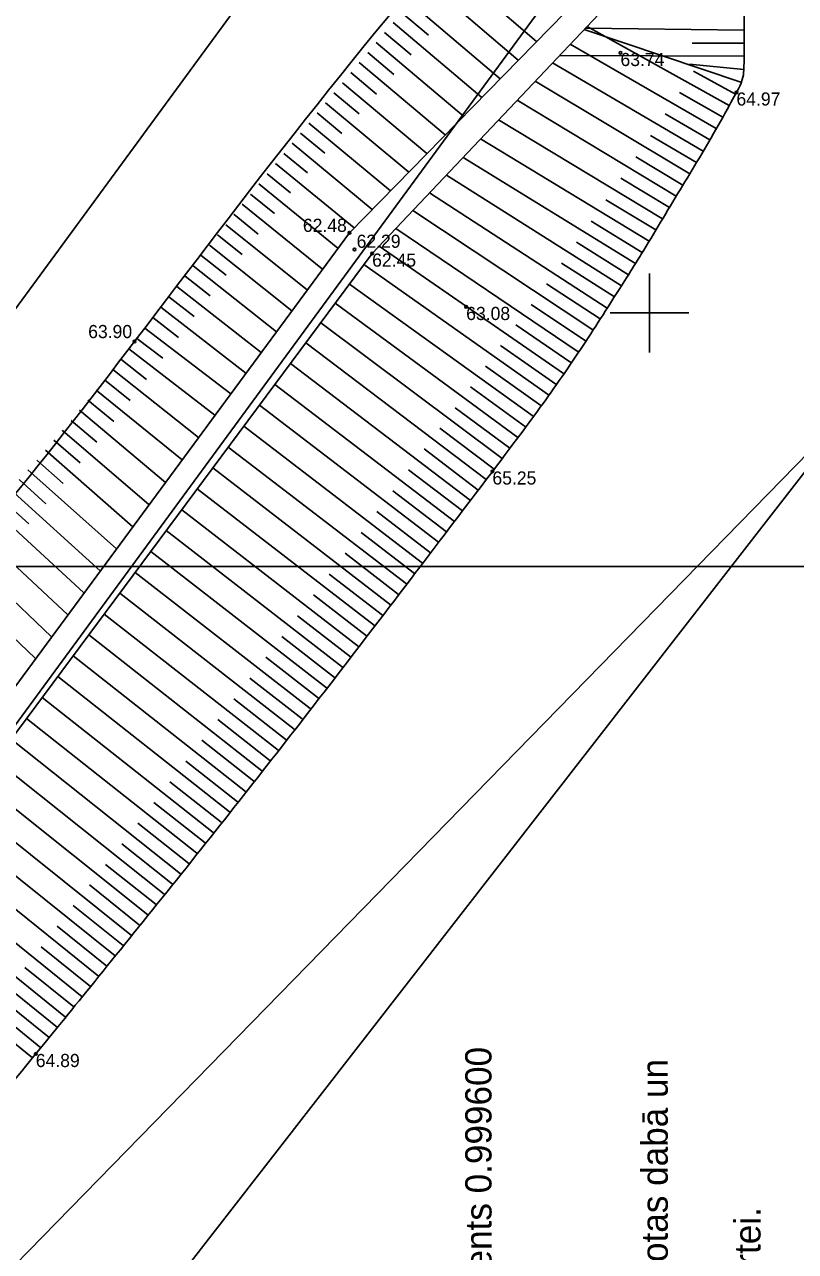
# Model space of a CAD drawing. Extents: x 616607 to 617499, y 408385 to 409695.
# Drawn here: x 617176.19 to 617205.56, y 409264.26 to 409310.99 of the extents above; entities that cross this region are included whole.
import ezdxf

# ---------------------------------------------------------------- set-up
doc = ezdxf.new("R2010")
doc.units = 0
for name, color, linetype in [('GEOD_ELEM_####_####_#', 7, 'Continuous'), ('HIDG_GRAV_####_####_#', 7, 'Continuous'), ('RAMI_PLAN_####_TKST_#', 7, 'Continuous'), ('RAMI_UZMR_####_####_#', 7, 'Continuous'), ('RELJ_AATZ_####_TKST_#', 7, 'Continuous'), ('RELJ_ELEM_####_####_#', 7, 'Continuous'), ('RELJ_NOGA_####_####_#', 7, 'Continuous'), ('ROBZ_UZMR_####_####_#', 7, 'Continuous')]:
    doc.layers.add(name, color=color, linetype=linetype)

# ---------------------------------------------------------------- blocks, each defined once
blk = doc.blocks.new('PKT')
at = {"layer": 'RELJ_ELEM_####_####_#'}
blk.add_circle((0, 0), 0.05, dxfattribs=at)
blk = doc.blocks.new('KRUSTS')
at = {"layer": 'GEOD_ELEM_####_####_#'}
for p, q in [((0, 1.5), (0, 0)), ((-1.5, 0), (0, 0)), ((0, 0), (0, -1.5)), ((0, 0), (1.5, 0))]:
    blk.add_line(p, q, dxfattribs=at)

msp = doc.modelspace()

# ---------------------------------------------------------------- linework, layer by layer
at = {"layer": 'HIDG_GRAV_####_####_#'}
for points in [[(617196.049, 409072.553), (617193.886, 409072.979), (617195.921, 409087.874), (617195.921, 409087.874), (617199.518, 409112.516), (617194.569, 409134.842), (617162.019, 409207.474), (617151.93, 409229.107), (617149.428, 409241.28), (617152.359, 409253.938), (617188.564, 409303.055), (617197.968, 409312.659), (617223.456, 409346.169), (617232.567, 409363.51), (617247.671, 409422.509), (617276.576, 409461.456), (617285.007, 409472.526), (617327.765, 409527.3)], [(617198.671, 409072.074), (617200.929, 409072.435), (617202.532, 409075.622), (617201.237, 409087.874), (617202.422, 409112.516), (617197.415, 409136.544), (617162.613, 409207.758), (617153.021, 409229.447), (617150.525, 409241.262), (617153.298, 409253.658), (617189.431, 409302.264), (617198.754, 409312.12), (617224.478, 409345.652), (617234.105, 409363.027), (617250.009, 409421.44), (617285.914, 409471.848), (617328.6, 409526.531)]]:
    msp.add_lwpolyline(points, dxfattribs=at)
at = {"layer": 'RAMI_PLAN_####_TKST_#'}
msp.add_line((617357.121, 409449.318), (617128.46, 409215.262), dxfattribs=at)
msp.add_lwpolyline([(617109.674, 409084.461), (617109.674, 409290.339), (617251.246, 409290.339), (617251.246, 409084.461), (617109.674, 409084.461)], dxfattribs=at)
at = {"layer": 'RAMI_UZMR_####_####_#'}
msp.add_lwpolyline([(617101.571, 408748.246), (617213.472, 409074.039), (617215.883, 409140.56), (617165.121, 409241.478), (617252.137, 409353.424), (617269.572, 409425.099), (617332.631, 409510.312), (617439.945, 409622.037), (617425.373, 409635.959), (617242.079, 409440.82), (617216.614, 409355.716), (617136.613, 409246.751), (617191.828, 409115.62), (617145.545, 408952.8)], dxfattribs=at)
at = {"layer": 'RELJ_NOGA_####_####_#'}
for p, q in [((617192.175, 409313.349), (617195.697, 409310.34)), ((617191.526, 409312.588), (617194.999, 409309.626)), ((617190.877, 409311.827), (617194.301, 409308.913)), ((617190.23, 409311.064), (617193.607, 409308.205)), ((617190.554, 409311.445), (617191.574, 409310.58)), ((617189.907, 409310.683), (617189.907, 409310.683)), ((617189.907, 409310.683), (617190.912, 409309.832)), ((617203.48, 409308.789), (617197.504, 409310.799)), ((617203.602, 409310.776), (617197.546, 409310.843)), ((617203.031, 409307.897), (617197.616, 409310.916)), ((617203.602, 409310.776), (617203.603, 409310.776)), ((617189.584, 409310.301), (617189.584, 409310.301)), ((617189.584, 409310.301), (617192.911, 409307.494)), ((617202.54, 409307.026), (617196.968, 409310.232)), ((617203.598, 409310.276), (617201.622, 409310.276)), ((617203.598, 409310.276), (617203.599, 409310.276)), ((617189.262, 409309.919), (617189.262, 409309.919)), ((617189.262, 409309.919), (617190.251, 409309.084)), ((617203.599, 409309.776), (617196.567, 409309.807)), ((617203.599, 409309.776), (617203.6, 409309.776)), ((617188.94, 409309.536), (617188.939, 409309.537)), ((617188.94, 409309.536), (617192.213, 409306.781)), ((617202.038, 409306.162), (617196.302, 409309.528)), ((617203.587, 409309.276), (617201.517, 409309.474)), ((617203.273, 409308.335), (617201.673, 409309.212)), ((617203.587, 409309.276), (617203.588, 409309.276)), ((617188.297, 409308.771), (617188.296, 409308.771)), ((617188.297, 409308.771), (617191.517, 409306.071)), ((617188.618, 409309.154), (617188.618, 409309.154)), ((617188.618, 409309.154), (617189.592, 409308.335)), ((617201.528, 409305.301), (617195.638, 409308.826)), ((617203.48, 409308.789), (617203.481, 409308.789)), ((617187.976, 409308.387), (617187.975, 409308.387)), ((617187.976, 409308.387), (617188.934, 409307.586)), ((617202.787, 409307.461), (617201.137, 409308.393)), ((617203.273, 409308.335), (617203.273, 409308.335)), ((617187.655, 409308.003), (617187.655, 409308.004)), ((617187.655, 409308.003), (617190.822, 409305.361)), ((617201.013, 409304.444), (617194.951, 409308.099)), ((617203.031, 409307.897), (617203.032, 409307.897)), ((617187.335, 409307.619), (617187.335, 409307.619)), ((617187.335, 409307.619), (617188.277, 409306.835)), ((617200.497, 409303.588), (617194.244, 409307.352)), ((617202.29, 409306.593), (617200.592, 409307.578)), ((617202.787, 409307.461), (617202.787, 409307.461)), ((617186.697, 409306.849), (617186.697, 409306.849)), ((617186.697, 409306.849), (617187.623, 409306.085)), ((617187.016, 409307.234), (617187.015, 409307.235)), ((617187.016, 409307.234), (617190.127, 409304.651)), ((617202.54, 409307.026), (617202.541, 409307.026)), ((617186.379, 409306.464), (617186.378, 409306.464)), ((617186.379, 409306.464), (617189.437, 409303.946)), ((617199.98, 409302.732), (617193.559, 409306.628)), ((617201.784, 409305.731), (617200.038, 409306.762)), ((617202.29, 409306.593), (617202.29, 409306.593)), ((617186.061, 409306.078), (617186.061, 409306.078)), ((617186.061, 409306.078), (617186.97, 409305.332)), ((617199.458, 409301.879), (617192.895, 409305.926)), ((617201.271, 409304.873), (617199.481, 409305.952)), ((617202.038, 409306.162), (617202.039, 409306.161)), ((617185.744, 409305.691), (617185.743, 409305.692)), ((617185.744, 409305.691), (617188.743, 409303.237)), ((617201.784, 409305.731), (617201.784, 409305.731)), ((617185.427, 409305.304), (617185.427, 409305.304)), ((617185.427, 409305.304), (617186.326, 409304.571)), ((617198.927, 409301.031), (617192.257, 409305.252)), ((617200.755, 409304.016), (617198.907, 409305.128)), ((617201.528, 409305.301), (617201.529, 409305.301)), ((617184.796, 409304.528), (617184.796, 409304.529)), ((617184.796, 409304.528), (617185.708, 409303.79)), ((617185.111, 409304.916), (617185.111, 409304.917)), ((617185.111, 409304.916), (617188.129, 409302.464)), ((617198.387, 409300.189), (617191.616, 409304.574)), ((617201.271, 409304.873), (617201.271, 409304.872)), ((617184.482, 409304.14), (617184.481, 409304.14)), ((617184.482, 409304.14), (617187.544, 409301.67)), ((617200.239, 409303.16), (617198.336, 409304.307)), ((617201.013, 409304.444), (617201.013, 409304.444)), ((617184.168, 409303.751), (617184.167, 409303.751)), ((617184.168, 409303.751), (617185.093, 409303.007)), ((617197.839, 409299.353), (617190.983, 409303.905)), ((617200.497, 409303.588), (617200.498, 409303.587)), ((617200.755, 409304.016), (617200.755, 409304.016)), ((617183.855, 409303.361), (617183.854, 409303.361)), ((617183.855, 409303.361), (617186.959, 409300.877)), ((617197.282, 409298.523), (617190.337, 409303.221)), ((617199.719, 409302.305), (617197.772, 409303.497)), ((617200.239, 409303.16), (617200.239, 409303.159)), ((617183.542, 409302.97), (617183.542, 409302.97)), ((617183.542, 409302.97), (617184.478, 409302.221)), ((617199.194, 409301.454), (617197.209, 409302.695)), ((617199.98, 409302.732), (617199.98, 409302.731)), ((617182.92, 409302.187), (617182.92, 409302.188)), ((617182.92, 409302.187), (617183.868, 409301.436)), ((617183.231, 409302.579), (617183.23, 409302.58)), ((617183.231, 409302.579), (617186.37, 409300.078)), ((617196.717, 409297.697), (617189.699, 409302.547)), ((617199.719, 409302.305), (617199.72, 409302.305)), ((617182.61, 409301.795), (617182.609, 409301.796)), ((617182.61, 409301.795), (617185.787, 409299.287)), ((617196.144, 409296.878), (617189.117, 409301.841)), ((617198.658, 409300.609), (617196.642, 409301.901)), ((617199.458, 409301.879), (617199.459, 409301.878)), ((617182.301, 409301.402), (617182.301, 409301.402)), ((617182.301, 409301.402), (617183.26, 409300.649)), ((617199.194, 409301.454), (617199.194, 409301.454)), ((617181.993, 409301.008), (617181.992, 409301.009)), ((617181.993, 409301.008), (617185.205, 409298.498)), ((617195.563, 409296.064), (617188.565, 409301.099)), ((617198.114, 409299.771), (617196.068, 409301.109)), ((617198.927, 409301.031), (617198.928, 409301.03)), ((617181.686, 409300.614), (617181.685, 409300.614)), ((617181.686, 409300.614), (617182.654, 409299.861)), ((617194.975, 409295.255), (617188.022, 409300.369)), ((617197.561, 409298.937), (617195.492, 409300.326)), ((617198.658, 409300.609), (617198.659, 409300.609)), ((617181.379, 409300.219), (617181.379, 409300.219)), ((617181.379, 409300.219), (617184.624, 409297.709)), ((617198.387, 409300.189), (617198.388, 409300.189)), ((617180.77, 409299.426), (617180.769, 409299.427)), ((617180.77, 409299.426), (617184.044, 409296.922)), ((617181.074, 409299.823), (617181.074, 409299.823)), ((617181.074, 409299.823), (617182.052, 409299.071)), ((617194.379, 409294.453), (617187.471, 409299.627)), ((617197.001, 409298.109), (617194.909, 409299.545)), ((617198.114, 409299.771), (617198.115, 409299.77)), ((617180.466, 409299.029), (617180.466, 409299.029)), ((617180.466, 409299.029), (617181.452, 409298.278)), ((617197.561, 409298.937), (617197.562, 409298.937)), ((617197.839, 409299.353), (617197.84, 409299.353)), ((617180.163, 409298.631), (617180.162, 409298.632)), ((617180.163, 409298.631), (617183.443, 409296.107)), ((617193.776, 409293.655), (617186.906, 409298.867)), ((617196.432, 409297.287), (617194.319, 409298.764)), ((617197.282, 409298.523), (617197.283, 409298.522)), ((617179.856, 409298.236), (617179.856, 409298.236)), ((617179.856, 409298.236), (617180.839, 409297.47)), ((617193.171, 409292.858), (617186.314, 409298.071)), ((617195.854, 409296.47), (617193.752, 409297.972)), ((617197.001, 409298.109), (617197.001, 409298.109)), ((617179.547, 409297.843), (617179.546, 409297.844)), ((617179.547, 409297.843), (617182.815, 409295.255)), ((617196.717, 409297.697), (617196.718, 409297.697)), ((617178.92, 409297.064), (617178.92, 409297.065)), ((617178.92, 409297.064), (617182.189, 409294.406)), ((617179.235, 409297.452), (617179.235, 409297.453)), ((617179.235, 409297.452), (617180.213, 409296.663)), ((617192.566, 409292.062), (617185.722, 409297.274)), ((617195.27, 409295.659), (617193.178, 409297.183)), ((617196.432, 409297.287), (617196.432, 409297.287)), ((617178.603, 409296.677), (617178.603, 409296.678)), ((617178.603, 409296.677), (617179.584, 409295.867)), ((617196.144, 409296.878), (617196.145, 409296.877)), ((617178.283, 409296.293), (617178.283, 409296.294)), ((617178.283, 409296.293), (617181.556, 409293.547)), ((617191.959, 409291.267), (617185.134, 409296.484)), ((617194.678, 409294.853), (617192.596, 409296.393)), ((617195.854, 409296.47), (617195.855, 409296.47)), ((617177.961, 409295.911), (617177.961, 409295.911)), ((617177.961, 409295.911), (617178.946, 409295.075)), ((617191.352, 409290.473), (617184.542, 409295.687)), ((617195.27, 409295.659), (617195.27, 409295.659)), ((617195.563, 409296.064), (617195.564, 409296.063)), ((617177.637, 409295.53), (617177.636, 409295.531)), ((617177.637, 409295.53), (617180.931, 409292.699)), ((617194.078, 409294.053), (617192.012, 409295.613)), ((617194.975, 409295.255), (617194.976, 409295.255)), ((617176.982, 409294.774), (617176.981, 409294.775)), ((617176.982, 409294.774), (617180.309, 409291.856)), ((617177.31, 409295.151), (617177.31, 409295.152)), ((617177.31, 409295.151), (617178.305, 409294.291)), ((617190.743, 409289.679), (617183.949, 409294.89)), ((617193.474, 409293.256), (617191.415, 409294.821)), ((617194.678, 409294.853), (617194.678, 409294.853)), ((617176.652, 409294.399), (617176.651, 409294.399)), ((617176.652, 409294.399), (617177.657, 409293.511)), ((617194.379, 409294.453), (617194.379, 409294.452)), ((617176.319, 409294.025), (617176.319, 409294.026)), ((617176.319, 409294.025), (617179.694, 409291.021)), ((617190.134, 409288.886), (617183.361, 409294.098)), ((617192.868, 409292.46), (617190.814, 409294.025)), ((617194.078, 409294.053), (617194.078, 409294.053)), ((617175.986, 409293.653), (617177.003, 409292.735)), ((617189.524, 409288.094), (617182.768, 409293.301)), ((617193.776, 409293.655), (617193.777, 409293.654)), ((617175.313, 409292.913), (617176.347, 409291.966)), ((617175.65, 409293.282), (617179.07, 409290.174)), ((617192.262, 409291.665), (617190.212, 409293.229)), ((617193.171, 409292.858), (617193.172, 409292.858)), ((617193.474, 409293.256), (617193.474, 409293.256)), ((617174.975, 409292.545), (617178.451, 409289.335)), ((617188.913, 409287.302), (617182.179, 409292.508)), ((617191.655, 409290.87), (617189.61, 409292.434)), ((617192.868, 409292.46), (617192.869, 409292.46)), ((617192.566, 409292.062), (617192.566, 409292.062)), ((617174.294, 409291.812), (617177.838, 409288.503)), ((617188.301, 409286.511), (617181.586, 409291.71)), ((617191.048, 409290.076), (617189.006, 409291.639)), ((617192.262, 409291.665), (617192.263, 409291.665)), ((617173.609, 409291.084), (617177.219, 409287.663)), ((617191.959, 409291.267), (617191.96, 409291.267)), ((617187.689, 409285.721), (617180.994, 409290.915)), ((617190.439, 409289.283), (617188.404, 409290.846)), ((617191.655, 409290.87), (617191.656, 409290.87)), ((617172.92, 409290.359), (617176.611, 409286.838)), ((617187.075, 409284.931), (617180.404, 409290.121)), ((617189.829, 409288.49), (617187.799, 409290.052)), ((617191.048, 409290.076), (617191.048, 409290.076)), ((617191.352, 409290.473), (617191.352, 409290.472)), ((617190.743, 409289.679), (617190.744, 409289.679)), ((617186.46, 409284.143), (617179.814, 409289.327)), ((617189.219, 409287.698), (617187.195, 409289.26)), ((617190.439, 409289.283), (617190.439, 409289.282)), ((617190.134, 409288.886), (617190.135, 409288.886)), ((617185.845, 409283.354), (617179.223, 409288.532)), ((617188.607, 409286.906), (617186.589, 409288.467)), ((617189.829, 409288.49), (617189.83, 409288.49)), ((617185.228, 409282.567), (617178.632, 409287.737)), ((617189.219, 409287.698), (617189.219, 409287.698)), ((617189.524, 409288.094), (617189.525, 409288.093)), ((617187.995, 409286.116), (617185.984, 409287.676)), ((617188.913, 409287.302), (617188.914, 409287.301)), ((617184.611, 409281.78), (617178.04, 409286.941)), ((617187.382, 409285.326), (617185.378, 409286.885)), ((617188.607, 409286.906), (617188.608, 409286.906)), ((617188.301, 409286.511), (617188.302, 409286.51)), ((617183.992, 409280.995), (617177.453, 409286.151)), ((617186.768, 409284.537), (617184.771, 409286.094)), ((617187.995, 409286.116), (617187.995, 409286.116)), ((617183.373, 409280.21), (617176.861, 409285.355)), ((617187.689, 409285.721), (617187.689, 409285.72)), ((617186.153, 409283.748), (617184.163, 409285.304)), ((617187.075, 409284.931), (617187.076, 409284.931)), ((617187.382, 409285.326), (617187.382, 409285.326)), ((617182.752, 409279.425), (617176.268, 409284.557)), ((617185.537, 409282.961), (617183.555, 409284.514)), ((617186.768, 409284.537), (617186.768, 409284.537)), ((617186.46, 409284.143), (617186.461, 409284.142)), ((617182.131, 409278.642), (617175.679, 409283.765)), ((617184.92, 409282.174), (617182.945, 409283.724)), ((617186.153, 409283.748), (617186.153, 409283.748)), ((617185.845, 409283.354), (617185.845, 409283.354)), ((617181.509, 409277.859), (617175.087, 409282.969)), ((617184.302, 409281.387), (617182.335, 409282.935)), ((617185.228, 409282.567), (617185.229, 409282.566)), ((617185.537, 409282.961), (617185.537, 409282.96)), ((617180.885, 409277.077), (617174.497, 409282.174)), ((617183.683, 409280.602), (617181.724, 409282.146)), ((617184.92, 409282.174), (617184.92, 409282.174)), ((617184.611, 409281.78), (617184.612, 409281.78)), ((617180.261, 409276.296), (617173.905, 409281.379)), ((617183.063, 409279.817), (617181.114, 409281.36)), ((617184.302, 409281.387), (617184.302, 409281.387)), ((617183.992, 409280.995), (617183.993, 409280.994)), ((617179.635, 409275.516), (617173.317, 409280.588)), ((617182.442, 409279.033), (617180.501, 409280.572)), ((617183.373, 409280.21), (617183.374, 409280.209)), ((617183.683, 409280.602), (617183.683, 409280.602)), ((617179.009, 409274.736), (617172.729, 409279.797)), ((617181.82, 409278.25), (617179.89, 409279.786)), ((617183.063, 409279.817), (617183.063, 409279.817)), ((617182.752, 409279.425), (617182.753, 409279.425)), ((617178.381, 409273.958), (617172.137, 409279.001)), ((617181.197, 409277.468), (617179.276, 409279)), ((617182.442, 409279.033), (617182.442, 409279.033)), ((617182.131, 409278.642), (617182.132, 409278.641)), ((617177.753, 409273.18), (617171.546, 409278.205)), ((617180.573, 409276.687), (617178.662, 409278.215)), ((617181.82, 409278.25), (617181.82, 409278.25)), ((617177.123, 409272.403), (617170.954, 409277.409)), ((617179.948, 409275.906), (617178.047, 409277.429)), ((617181.197, 409277.468), (617181.197, 409277.468)), ((617181.509, 409277.859), (617181.509, 409277.859)), ((617180.885, 409277.077), (617180.886, 409277.077)), ((617176.493, 409271.627), (617170.363, 409276.614)), ((617179.322, 409275.126), (617177.432, 409276.646)), ((617180.573, 409276.687), (617180.573, 409276.686)), ((617180.261, 409276.296), (617180.262, 409276.295)), ((617178.695, 409274.347), (617176.816, 409275.861)), ((617179.948, 409275.906), (617179.948, 409275.906)), ((617178.067, 409273.569), (617176.199, 409275.078)), ((617179.322, 409275.126), (617179.323, 409275.126)), ((617179.635, 409275.516), (617179.636, 409275.515)), ((617179.009, 409274.736), (617179.01, 409274.736)), ((617177.438, 409272.792), (617175.581, 409274.295)), ((617178.695, 409274.347), (617178.695, 409274.347)), ((617178.381, 409273.958), (617178.382, 409273.957)), ((617176.808, 409272.015), (617174.963, 409273.514)), ((617178.067, 409273.569), (617178.067, 409273.569)), ((617177.438, 409272.792), (617177.438, 409272.791)), ((617177.753, 409273.18), (617177.754, 409273.179)), ((617177.123, 409272.403), (617177.124, 409272.402)), ((617176.808, 409272.015), (617176.808, 409272.015)), ((617176.493, 409271.627), (617176.493, 409271.626))]:
    msp.add_line(p, q, dxfattribs=at)
for points in [[(617148.095, 409250.281), (617149.367, 409254.282), (617150.639, 409258.284), (617151.912, 409262.285), (617156.597, 409277.022), (617171.021, 409286.603), (617180.379, 409298.915), (617194.802, 409317.89), (617212.921, 409334.355), (617223.034, 409356.295), (617225.913, 409362.541), (617226.817, 409369.327), (617228.782, 409375.821), (617233.86, 409392.605), (617237.843, 409409.628), (617244.376, 409426.063), (617252.258, 409445.895), (617268.673, 409460.708), (617281.86, 409477.296), (617294.583, 409493.301), (617307.725, 409508.821), (617320.496, 409524.825), (617320.543, 409524.885), (617320.584, 409524.948), (617320.623, 409525.013), (617320.843, 409525.374), (617320.906, 409525.909), (617320.728, 409526.275), (617320.636, 409526.463), (617320.388, 409526.567), (617320.294, 409526.764), (617319.61, 409528.184), (617318.926, 409529.604), (617318.242, 409531.024)], [(617336.806, 409523.735), (617334.087, 409521.174), (617331.368, 409518.613), (617328.65, 409516.053), (617321.193, 409509.03), (617314.57, 409501.094), (617308.568, 409492.793), (617305.546, 409488.614), (617302.537, 409484.426), (617299.516, 409480.247), (617296.49, 409476.063), (617293.469, 409471.875), (617290.436, 409467.695), (617287.772, 409464.025), (617284.965, 409460.461), (617282.252, 409456.826), (617279.55, 409453.205), (617276.887, 409449.558), (617274.256, 409445.882), (617271.624, 409442.206), (617269.17, 409438.414), (617266.782, 409434.573), (617265.581, 409432.642), (617264.455, 409430.674), (617263.346, 409428.69), (617262.228, 409426.69), (617261.169, 409424.668), (617260.166, 409422.606), (617258.56, 409419.302), (617257.132, 409415.931), (617255.903, 409412.47), (617254.682, 409409.035), (617253.531, 409405.585), (617252.579, 409402.073), (617251.627, 409398.563), (617250.683, 409395.052), (617249.746, 409391.538), (617248.81, 409388.023), (617247.876, 409384.508), (617246.956, 409380.989), (617246.456, 409379.078), (617246.028, 409377.149), (617245.649, 409375.21), (617245.269, 409373.268), (617244.984, 409371.31), (617244.622, 409369.366), (617244.259, 409367.42), (617243.878, 409365.48), (617243.456, 409363.545), (617243.245, 409362.576), (617242.967, 409361.625), (617242.691, 409360.672), (617242.413, 409359.713), (617242.093, 409358.772), (617241.734, 409357.838), (617241.092, 409356.173), (617240.315, 409354.578), (617239.389, 409353.048), (617238.465, 409351.519), (617237.498, 409350.034), (617236.402, 409348.636), (617235.3, 409347.23), (617234.195, 409345.828), (617233.083, 409344.431), (617231.973, 409343.038), (617230.863, 409341.647), (617229.743, 409340.262), (617227.764, 409337.815), (617225.693, 409335.438), (617223.461, 409333.217), (617221.215, 409330.983), (617218.873, 409328.856), (617216.607, 409326.646), (617214.346, 409324.442), (617212.093, 409322.231), (617209.875, 409319.98), (617208.771, 409318.86), (617207.791, 409317.635), (617206.772, 409316.432), (617205.753, 409315.229), (617204.825, 409314.017), (617203.96, 409312.646), (617203.768, 409312.342), (617203.633, 409312.004), (617203.62, 409311.655), (617203.607, 409311.284), (617203.603, 409310.913), (617203.599, 409310.542), (617203.595, 409310.167), (617203.603, 409309.793), (617203.596, 409309.419), (617203.588, 409309.066), (617203.48, 409308.714), (617203.309, 409308.4), (617202.615, 409307.13), (617201.9, 409305.914), (617201.16, 409304.689), (617200.419, 409303.462), (617199.689, 409302.232), (617198.921, 409301.021), (617197.385, 409298.6), (617195.744, 409296.251), (617194.012, 409293.966), (617188.331, 409286.47), (617182.548, 409279.072), (617176.617, 409271.78), (617175.091, 409269.904), (617173.565, 409268.03), (617172.006, 409266.181), (617170.46, 409264.348), (617168.875, 409262.548), (617167.326, 409260.717), (617165.749, 409258.854), (617164.19, 409256.978), (617162.652, 409255.082), (617161.86, 409254.106), (617161.109, 409253.1), (617160.341, 409252.105), (617159.552, 409251.081), (617158.796, 409250.055), (617158.061, 409248.97), (617157.091, 409247.54), (617156.549, 409245.874), (617156.301, 409244.175), (617156.178, 409243.327), (617156.153, 409242.478), (617156.175, 409241.631), (617156.198, 409240.798), (617156.24, 409239.966), (617156.347, 409239.134), (617156.709, 409236.311), (617157.141, 409233.481), (617158.294, 409230.866), (617161.329, 409223.986), (617164.552, 409217.339), (617167.894, 409210.677), (617170.758, 409204.966), (617173.578, 409199.236), (617176.506, 409193.56), (617179.423, 409187.907), (617182.384, 409182.277), (617185.301, 409176.624), (617188.243, 409170.922), (617191.171, 409165.213), (617194.071, 409159.489), (617195.541, 409156.585), (617196.952, 409153.652), (617198.382, 409150.727), (617199.832, 409147.761), (617201.227, 409144.774), (617202.61, 409141.772), (617203.681, 409139.449), (617204.533, 409137.047), (617205.282, 409134.589), (617206.022, 409132.164), (617206.554, 409129.71), (617206.943, 409127.212), (617207.329, 409124.726), (617207.611, 409122.242), (617207.809, 409119.738), (617208.005, 409117.248), (617208.126, 409114.753), (617208.097, 409112.263), (617208.074, 409110.266), (617207.983, 409108.256), (617207.635, 409106.282), (617207.283, 409104.281), (617206.913, 409102.294), (617206.558, 409100.3), (617206.203, 409098.306), (617205.85, 409096.331), (617205.506, 409094.315), (617205.165, 409092.324), (617205.06, 409090.322), (617205.116, 409088.325), (617205.171, 409086.355), (617205.316, 409084.384), (617205.484, 409082.414), (617205.653, 409080.435), (617205.914, 409078.469), (617206.09, 409076.495), (617206.126, 409076.085), (617206.005, 409075.66), (617206.103, 409075.26)]]:
    msp.add_open_spline(points, degree=3, dxfattribs=at)
at = {"layer": 'ROBZ_UZMR_####_####_#'}
for points in [[(617232.583, 409073.745), (617196.025, 409075.262), (617200.886, 409119.423), (617196.507, 409136.07), (617150.138, 409230.13), (617148.652, 409247.272), (617201.229, 409318.934), (617233.453, 409357.938), (617244.928, 409391.934), (617250.98, 409414.497), (617255.789, 409432.426), (617326.39, 409521.291), (617332.188, 409529.592), (617332.358, 409529.835), (617335.391, 409534.333), (617341.051, 409533.641), (617349.913, 409536.856), (617370.73, 409556.7), (617378.749, 409547.935), (617381.343, 409545.1)], [(617175.508, 409335.542), (617196.893, 409321.733), (617201.229, 409318.934), (617148.652, 409247.272), (617118.895, 409264.376)]]:
    msp.add_lwpolyline(points, dxfattribs=at)

# ---------------------------------------------------------------- block references
at = {"layer": 'GEOD_ELEM_####_####_#'}
msp.add_blockref('KRUSTS', (617200, 409300), dxfattribs=at)
at = {"layer": 'RELJ_ELEM_####_####_#'}
for p in [(617198.891, 409309.904), (617203.309, 409308.4), (617188.564, 409303.055), (617188.756, 409302.416), (617189.431, 409302.264), (617193.013, 409300.231), (617180.379, 409298.915), (617194.012, 409293.966), (617176.617, 409271.78)]:
    msp.add_blockref('PKT', p, dxfattribs=at)

# ---------------------------------------------------------------- texts
at = {"layer": 'RAMI_PLAN_####_TKST_#'}
for s, p in [('Mēroga koeficients 0.999600', (617193.977, 409254.875)), ('4. Inženiertehniskās komunikācijas daļēji apsekotas dabā un ', (617200.692, 409235.759)), ('5. Kadastra informācija atbilst VZD kadastra kartei.', (617204.225, 409235.845))]:
    msp.add_text(s, height=1, rotation=90, dxfattribs=at).set_placement(p)
at = {"layer": 'RELJ_AATZ_####_TKST_#'}
for s, p in [('63.74', (617198.891, 409309.404)), ('64.97', (617203.309, 409307.9)), ('62.48', (617186.792, 409303.088)), ('62.29', (617188.839, 409302.482)), ('62.45', (617189.431, 409301.764)), ('63.08', (617193.013, 409299.731)), ('63.90', (617178.613, 409299.043)), ('65.25', (617194.012, 409293.466)), ('64.89', (617176.617, 409271.28))]:
    msp.add_text(s, height=0.5, dxfattribs=at).set_placement(p)

doc.saveas('drawing.dxf')
